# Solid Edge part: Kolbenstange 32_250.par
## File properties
Username: ahadarics
Dokumentum tartalom típus: 0
Author: ahadarics
Last saved by: ahadarics
Revision: 86
Sűrűség: 0,000 kg/m^3
Pontosság: 0,990
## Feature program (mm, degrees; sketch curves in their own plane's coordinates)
base feature "unnamed BaseFeature 1"
thread "unnamed Thread 1"
chamfer "Letörés_1"  SetBackValue2 = 20 deg
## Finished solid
Body 1: solid body, 19 faces, 27 edges, 11 vertices.
  Faces by surface: plane 8, cylinder 5, cone 3, torus 3
  Edges by curve: circle 15, line 7, curve on surface 3, ellipse 2
Bounding box of the edges (mm; curved faces can reach further): 32.000 x 32.000 x 365.500, from (-16, -16, -50.25) to (16, 16, 315.25).
Cylindrical faces by radius (mm): R3.95 x1, R5 x1, R5.8 x1, R6 x1, R16 x1
Conical faces (half-angle, radius in mm at the cone's reference point): 20 deg R5 x1, 30 deg R5.9 x1, 60 deg R4.475 x1
Toroidal faces (ring radius, tube radius in mm): R4.35 r0.4 x2, R4.6 r1.2 x1
Planar faces by outward normal: +x 1, +z 3, -x 1, -z 1, oblique 2
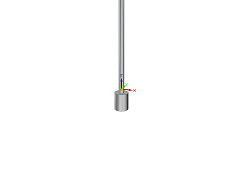
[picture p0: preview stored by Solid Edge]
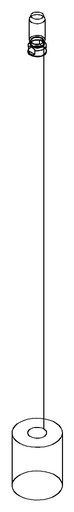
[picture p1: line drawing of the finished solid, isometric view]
